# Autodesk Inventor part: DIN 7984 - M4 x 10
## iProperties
Created: 2009-02
Part Number: DIN 7984 - M4 x 10
Material: Stahl, weich, unlegiert
Description: Zylinderkopfschraube
Document SubType Name: Modeling
Standard: DIN 7984
Designer: UR
Standard Revision: 1985
Standards Organization: DIN
Language: de-DE
Size Designation: M4 x 10
Categories: <MemberInstance><Categories><Category DisplayName="Verbindungselemente" InternalName="e4da775c-781d-43d5-af7c-5136215cf5a6" Mnemonic="FSTN"><Category DisplayNam
Density: 1 g/cm^3
IsCustomPart: 0
Author: UR
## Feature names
1. Körper [Revolution]
2. Loch [Extrusion]
3. Rundung1 [Fillet]
4. Fase1 [Chamfer]
5. Fillet2
